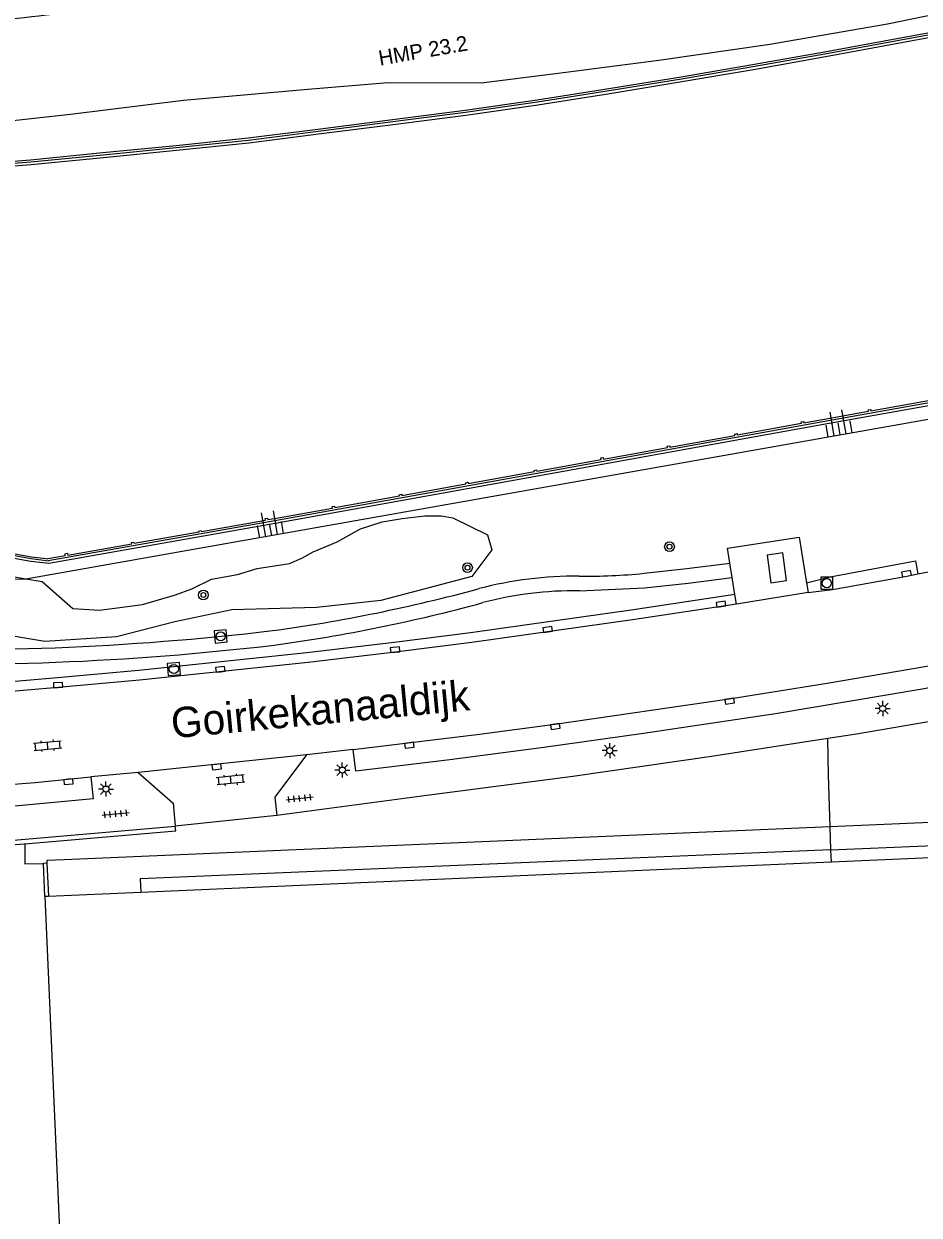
# Model space of a CAD drawing. Extents: x 132999 to 136000, y 398499 to 400501.
# Drawn here: x 133349.3 to 133423.1, y 398750.4 to 398848.7 of the extents above; entities that cross this region are included whole.
import ezdxf

# ---------------------------------------------------------------- set-up
doc = ezdxf.new("R2010")
doc.units = 0
for name, color, linetype in [('gg-afsc-hekwerk', 7, 'Continuous'), ('gg-afsc-muur', 7, 'Continuous'), ('gg-anno-openbare ruimte label', 7, 'Continuous'), ('gg-bbg-hoofdgebouw', 7, 'Continuous'), ('gg-bbg-luifel en loopbrug', 7, 'Continuous'), ('gg-bbg-onder overbouw', 7, 'Continuous'), ('gg-bbg-pand overbouw', 7, 'Continuous'), ('gg-knt-BGT kruinlijn', 7, 'Continuous'), ('gg-knt-verharding', 7, 'Continuous'), ('gg-knt-verharding nz', 7, 'Continuous'), ('gg-kwrk-betonelement', 7, 'Continuous'), ('gt-anno-nummer hm paal', 7, 'Continuous'), ('gt-grn-groengrens', 7, 'Continuous'), ('gt-symb-boom', 7, 'Continuous'), ('gt-symb-klinker verharding', 7, 'Continuous'), ('gt-symb-kolk', 7, 'Continuous'), ('gt-symb-lichtmast', 7, 'Continuous'), ('gt-symb-rioolschacht', 7, 'Continuous'), ('gt-symb-talud symbool', 7, 'Continuous'), ('gt-symb-tegel verharding', 7, 'Continuous'), ('gx-grn-maaiveld', 7, 'Continuous')]:
    doc.layers.add(name, color=color, linetype=linetype)

# ---------------------------------------------------------------- blocks, each defined once
blk = doc.blocks.new('gt0-TALUD_1')
at = {"layer": 'gt-symb-talud symbool'}
for p, q in [((-1, -1), (-1, 0)), ((-0.5, -2), (-0.5, 0)), ((0, -1), (0, 0)), ((0.5, -2), (0.5, 0)), ((1, -1), (1, 0))]:
    blk.add_line(p, q, dxfattribs=at)
blk = doc.blocks.new('gt0-RS')
at = {"layer": 'gt-symb-rioolschacht'}
blk.add_lwpolyline([(-0.5, -0.5), (0.5, -0.5), (0.5, 0.5), (-0.5, 0.5)], close=True, dxfattribs=at)
blk.add_circle((0, 0), 0.375, dxfattribs=at)
blk = doc.blocks.new('gt0-KOLK')
at = {"layer": 'gt-symb-kolk'}
blk.add_lwpolyline([(0, 0), (0.375, 0), (0.375, 0.4), (-0.375, 0.4), (-0.375, 0), (0, 0)], dxfattribs=at)
blk = doc.blocks.new('gt0-BOOM')
at = {"layer": 'gt-symb-boom'}
for radius in [0.4, 0.2]:
    blk.add_circle((0, 0), radius, dxfattribs=at)
blk = doc.blocks.new('gt0-LMAST')
at = {"layer": 'gt-symb-lichtmast'}
for p, q in [((-0.182, 0.173), (-0.447, 0.438)), ((-0.005, 0.246), (-0.005, 0.621)), ((0.172, 0.173), (0.437, 0.438)), ((-0.255, -0.004), (-0.63, -0.004)), ((-0.182, -0.181), (-0.447, -0.446)), ((-0.005, -0.254), (-0.005, -0.629)), ((0.437, -0.446), (0.172, -0.181)), ((0.245, -0.004), (0.62, -0.004))]:
    blk.add_line(p, q, dxfattribs=at)
blk.add_circle((-0.005, -0.004), 0.25, dxfattribs=at)
blk = doc.blocks.new('gt0-KL1')
at = {"layer": 'gt-symb-klinker verharding'}
for p, q in [((-1.15, 0.3), (1.15, 0.3)), ((-1, -0.3), (-1, 0.3)), ((-0.5, 0.3), (-0.5, 0.45)), ((0, -0.3), (0, 0.3)), ((0.5, 0.3), (0.5, 0.45)), ((1, -0.3), (1, 0.3)), ((-1.15, -0.3), (1.15, -0.3)), ((-0.5, -0.45), (-0.5, -0.3)), ((0.5, -0.45), (0.5, -0.3))]:
    blk.add_line(p, q, dxfattribs=at)
blk = doc.blocks.new('gt0-TEG1')
at = {"layer": 'gt-symb-tegel verharding'}
for p, q in [((-1.125, 0), (1.125, 0)), ((-0.9, -0.25), (-0.9, 0.25)), ((-0.45, -0.25), (-0.45, 0.25)), ((0, -0.25), (0, 0.25)), ((0.45, -0.25), (0.45, 0.25)), ((0.9, -0.25), (0.9, 0.25))]:
    blk.add_line(p, q, dxfattribs=at)

msp = doc.modelspace()

# ---------------------------------------------------------------- linework, layer by layer
at = {"layer": 'gg-afsc-hekwerk'}
for p, q in [((133361.818, 398782.084), (133361.767, 398782.456)), ((133415.867, 398780.523), (133415.805, 398782.401)), ((133349.346, 398780.995), (133361.818, 398782.084)), ((133415.901, 398779.498), (133415.867, 398780.523))]:
    msp.add_line(p, q, dxfattribs=at)
for points in [[(133415.609, 398789.703), (133415.609, 398789.722), (133417.98, 398790.069), (133423.912, 398791.103), (133446.77, 398795.458), (133462.485, 398798.488), (133468.883, 398799.753)], [(133415.805, 398782.401), (133415.664, 398786.661), (133415.609, 398789.703)], [(133293.847, 398778.301), (133296.188, 398778.325), (133308.274, 398778.577), (133322.783, 398779.123), (133337.252, 398780.056), (133349.303, 398780.991), (133349.346, 398780.995)], [(133349.346, 398780.995), (133349.358, 398779.359), (133350.893, 398779.37)]]:
    msp.add_lwpolyline(points, dxfattribs=at)
at = {"layer": 'gg-afsc-muur'}
msp.add_line((133351.01, 398776.646), (133350.893, 398779.37), dxfattribs=at)
for points in [[(133472.587, 398856.696), (133472.231, 398856.63), (133456.851, 398853.792), (133440.667, 398850.81), (133421.336, 398847.253), (133415.37, 398846.154), (133409.432, 398845.103), (133403.529, 398844.097), (133397.579, 398843.125), (133391.652, 398842.19), (133385.708, 398841.335), (133379.726, 398840.569), (133373.787, 398839.803), (133367.81, 398839.049), (133361.852, 398838.439), (133355.825, 398837.84), (133349.854, 398837.251), (133343.856, 398836.777), (133337.878, 398836.337)], [(133464.842, 398824.728), (133438.592, 398819.995), (133415.21, 398815.818), (133393.006, 398811.801), (133369.98, 398807.654), (133351.29, 398804.346)], [(133351.292, 398804.337), (133351.107, 398804.36), (133349.873, 398804.514), (133337.66, 398806.703)], [(133350.893, 398779.37), (133350.891, 398779.417), (133351.181, 398779.425)]]:
    msp.add_lwpolyline(points, dxfattribs=at)
at = {"layer": 'gg-bbg-hoofdgebouw'}
for p, q in [((133351.302, 398776.659), (133351.01, 398776.646)), ((133358.917, 398776.994), (133351.302, 398776.659))]:
    msp.add_line(p, q, dxfattribs=at)
msp.add_lwpolyline([(133351.01, 398776.646), (133353.201, 398726.602), (133355.607, 398671.444)], dxfattribs=at)
at = {"layer": 'gg-bbg-luifel en loopbrug'}
for p, q in [((133439.039, 398783.401), (133415.805, 398782.401)), ((133351.181, 398779.425), (133351.302, 398776.659))]:
    msp.add_line(p, q, dxfattribs=at)
msp.add_lwpolyline([(133415.805, 398782.401), (133352.611, 398779.682), (133351.174, 398779.618), (133351.181, 398779.425)], dxfattribs=at)
at = {"layer": 'gg-bbg-onder overbouw'}
for p, q in [((133439.39, 398780.53), (133415.901, 398779.498)), ((133415.901, 398779.498), (133358.917, 398776.994))]:
    msp.add_line(p, q, dxfattribs=at)
at = {"layer": 'gg-bbg-pand overbouw'}
for points in [[(133415.867, 398780.523), (133439.348, 398781.513), (133439.39, 398780.53)], [(133415.867, 398780.523), (133358.867, 398778.119), (133358.917, 398776.994)]]:
    msp.add_lwpolyline(points, dxfattribs=at)
at = {"layer": 'gg-knt-BGT kruinlijn'}
for p, q in [((133434.733, 398851.533), (133420.546, 398848.638)), ((133420.546, 398848.638), (133410.837, 398846.952)), ((133410.837, 398846.952), (133401.675, 398845.649)), ((133401.675, 398845.649), (133393.136, 398844.539)), ((133393.136, 398844.539), (133387.01, 398843.779)), ((133379.334, 398843.798), (133372.703, 398843.259)), ((133387.01, 398843.779), (133379.334, 398843.798)), ((133362.434, 398842.34), (133353.116, 398841.195)), ((133372.703, 398843.259), (133362.434, 398842.34)), ((133353.116, 398841.195), (133343.898, 398840.185))]:
    msp.add_line(p, q, dxfattribs=at)
for points in [[(133349.433, 398802.862), (133445.51, 398819.867), (133468.28, 398824.1)], [(133339.496, 398804.853), (133346.928, 398803.306), (133349.433, 398802.862)]]:
    msp.add_lwpolyline(points, dxfattribs=at)
at = {"layer": 'gg-knt-verharding'}
for p, q in [((133413.448, 398805.107), (133413.858, 398802.529)), ((133407.71, 398802.984), (133407.521, 398804.17)), ((133407.935, 398801.569), (133407.71, 398802.984)), ((133413.858, 398802.529), (133413.984, 398801.739)), ((133408.061, 398800.779), (133407.935, 398801.569)), ((133413.984, 398801.739), (133408.061, 398800.779)), ((133376.446, 398788.78), (133372.609, 398788.35)), ((133358.702, 398786.891), (133354.809, 398786.521)), ((133382.532, 398784.983), (133370.145, 398783.342)), ((133370.145, 398783.342), (133361.767, 398782.456))]:
    msp.add_line(p, q, dxfattribs=at)
for points in [[(133423.047, 398803.275), (133452.544, 398808.978), (133474.794, 398813.324)], [(133407.521, 398804.17), (133407.326, 398805.392), (133413.258, 398806.303), (133413.448, 398805.107)], [(133413.984, 398801.739), (133415.983, 398802.003), (133422.134, 398803.099), (133423.047, 398803.275)], [(133463.844, 398801.547), (133423.552, 398793.788), (133411.281, 398791.735), (133400.408, 398790.097), (133392.18, 398788.941), (133384.422, 398787.939), (133376.657, 398786.994), (133376.446, 398788.78)], [(133408.061, 398800.779), (133399.68, 398799.511), (133386.228, 398797.628), (133379.925, 398796.818), (133372.72, 398795.979), (133358.816, 398794.519), (133352.117, 398793.894), (133344.405, 398793.24), (133336.688, 398792.652), (133329.453, 398792.172), (133322.214, 398791.768), (133314.995, 398791.448), (133301.531, 398791.018)], [(133415.609, 398789.703), (133405.998, 398788.211), (133394.566, 398786.562), (133382.532, 398784.983)], [(133372.609, 398788.35), (133369.978, 398784.861), (133370.145, 398783.342)], [(133354.809, 398786.521), (133354.993, 398784.706), (133348.837, 398784.149), (133342.676, 398783.648), (133335.69, 398783.146), (133328.699, 398782.703), (133322.207, 398782.349), (133315.712, 398782.056), (133309.014, 398781.816), (133302.314, 398781.644), (133297.377, 398781.567)], [(133358.702, 398786.891), (133361.607, 398784.352), (133361.767, 398782.456)], [(133293.625, 398778.674), (133296.61, 398778.705), (133303.069, 398778.829), (133315.055, 398779.202), (133327.021, 398779.769), (133338.335, 398780.485), (133344.269, 398780.936), (133361.767, 398782.456)]]:
    msp.add_lwpolyline(points, dxfattribs=at)
msp.add_arc((133297.102, 399310.987), 464.733, 274.69579, 277.04022, dxfattribs=at)
at = {"layer": 'gg-knt-verharding nz'}
msp.add_line((133372.609, 398788.35), (133358.702, 398786.891), dxfattribs=at)
for points in [[(133376.446, 398788.78), (133386.883, 398790.046), (133393.094, 398790.882), (133407.471, 398792.974), (133415.547, 398794.27), (133423.613, 398795.63), (133464.293, 398803.482)], [(133297.321, 398783.36), (133301.036, 398783.42), (133308.5, 398783.612), (133315.537, 398783.857), (133322.572, 398784.175), (133330.011, 398784.598), (133337.447, 398785.086), (133350.204, 398786.068), (133354.809, 398786.521)]]:
    msp.add_lwpolyline(points, dxfattribs=at)
at = {"layer": 'gg-kwrk-betonelement'}
msp.add_lwpolyline([(133412.201, 398802.738), (133411.887, 398805.015), (133410.596, 398804.829), (133410.91, 398802.552), (133412.201, 398802.738)], dxfattribs=at)
at = {"layer": 'gt-grn-groengrens'}
msp.add_line((133369.941, 398797.406), (133369.92, 398797.403), dxfattribs=at)
for points in [[(133349.433, 398802.862), (133350.791, 398802.637), (133353.315, 398800.434), (133355.517, 398800.273), (133359.062, 398800.757), (133361.801, 398801.562), (133363.144, 398802.046), (133364.755, 398802.851), (133366.903, 398803.227), (133368.514, 398803.711), (133371.2, 398804.14), (133372.22, 398804.57), (133373.133, 398805.107), (133375.121, 398805.913), (133377.054, 398806.987), (133378.826, 398807.578), (133380.491, 398807.846), (133382.371, 398808.061), (133383.714, 398808.061), (133384.681, 398807.9), (133387.527, 398806.503), (133387.897, 398805.259), (133386.236, 398803.075), (133378.734, 398801.08), (133373.416, 398800.511), (133366.437, 398800.321), (133361.736, 398799.324), (133356.913, 398798.071), (133351.006, 398797.695), (133346.87, 398798.394)], [(133400.444, 398803.325), (133403.988, 398803.711), (133407.521, 398804.17)], [(133413.858, 398802.529), (133415.814, 398803.038), (133422.84, 398804.347), (133423.047, 398803.275)], [(133395.112, 398801.886), (133400.471, 398802.122), (133404.093, 398802.515), (133407.71, 398802.984)], [(133347.825, 398802.837), (133349.433, 398802.862)], [(133407.935, 398801.569), (133399.565, 398800.303), (133386.122, 398798.421), (133379.828, 398797.612), (133372.632, 398796.774), (133358.737, 398795.315), (133352.046, 398794.691), (133344.341, 398794.037), (133336.631, 398793.45), (133329.404, 398792.971), (133322.174, 398792.567), (133314.965, 398792.247), (133301.512, 398791.818)]]:
    msp.add_lwpolyline(points, dxfattribs=at)
for centre, radius, start, end in [((133394.817, 398771.442), 31.645, 89.48935, 104.61737), ((133395.54, 398853.106), 50.022, 269.49463, 275.62589), ((133351.77, 398930.798), 133.424, 277.75701, 285.2348), ((133394.829, 398771.359), 30.529, 89.46846, 104.58154), ((133351.782, 398930.751), 134.576, 277.75481, 285.23377), ((133343.169, 399023.022), 225.999, 267.64387, 276.76194), ((133343.168, 399023.096), 227.273, 267.64495, 276.75988)]:
    msp.add_arc(centre, radius, start, end, dxfattribs=at)
at = {"layer": 'gx-grn-maaiveld'}
for points in [[(133337.863, 398836.536), (133343.841, 398836.976), (133349.836, 398837.45), (133355.805, 398838.039), (133361.832, 398838.638), (133367.787, 398839.248), (133373.762, 398840.001), (133379.701, 398840.767), (133385.681, 398841.533), (133391.622, 398842.388), (133397.547, 398843.322), (133403.496, 398844.294), (133409.398, 398845.3), (133415.334, 398846.351), (133421.3, 398847.45), (133440.631, 398851.007), (133456.815, 398853.989), (133472.195, 398856.827), (133472.604, 398856.903)], [(133337.892, 398836.137), (133343.871, 398836.577), (133349.871, 398837.052), (133355.844, 398837.641), (133361.872, 398838.24), (133367.832, 398838.851), (133373.813, 398839.604), (133379.752, 398840.37), (133385.735, 398841.137), (133391.682, 398841.993), (133397.61, 398842.927), (133403.562, 398843.9), (133409.467, 398844.906), (133415.405, 398845.957), (133421.373, 398847.057), (133440.703, 398850.614), (133456.888, 398853.596), (133472.268, 398856.434), (133472.669, 398856.508)], [(133337.611, 398806.534), (133349.847, 398804.341), (133351.086, 398804.187), (133351.324, 398804.157), (133351.325, 398804.149), (133370.015, 398807.457), (133393.041, 398811.604), (133415.245, 398815.621), (133438.627, 398819.798), (133464.878, 398824.531)], [(133337.71, 398806.872), (133349.899, 398804.687), (133351.129, 398804.534), (133351.26, 398804.518), (133351.255, 398804.543), (133352.695, 398804.798), (133352.671, 398804.94), (133352.868, 398804.974), (133352.892, 398804.833), (133358.172, 398805.767), (133358.155, 398805.866), (133358.352, 398805.9), (133358.369, 398805.802), (133363.727, 398806.75), (133363.717, 398806.811), (133363.914, 398806.845), (133363.924, 398806.785), (133369.205, 398807.72), (133369.182, 398807.852), (133369.379, 398807.886), (133369.402, 398807.755), (133369.945, 398807.851), (133374.735, 398808.714), (133374.715, 398808.83), (133374.912, 398808.864), (133374.932, 398808.749), (133380.268, 398809.71), (133380.251, 398809.812), (133380.448, 398809.846), (133380.465, 398809.746), (133385.75, 398810.697), (133385.733, 398810.799), (133385.93, 398810.833), (133385.947, 398810.733), (133391.401, 398811.715), (133391.383, 398811.818), (133391.58, 398811.852), (133391.597, 398811.75), (133396.898, 398812.708), (133396.873, 398812.852), (133397.07, 398812.886), (133397.094, 398812.744), (133402.386, 398813.701), (133402.365, 398813.823), (133402.562, 398813.857), (133402.583, 398813.737), (133407.945, 398814.707), (133407.926, 398814.818), (133408.123, 398814.852), (133408.142, 398814.742), (133413.443, 398815.702), (133413.421, 398815.829), (133413.618, 398815.863), (133413.64, 398815.737), (133415.174, 398816.015), (133418.968, 398816.693), (133418.947, 398816.817), (133419.144, 398816.851), (133419.165, 398816.728), (133424.51, 398817.683)]]:
    msp.add_lwpolyline(points, dxfattribs=at)

# ---------------------------------------------------------------- block references
at = {"layer": 'gt-symb-boom'}
for p in [(133402.546, 398805.521), (133385.882, 398803.795), (133364.091, 398801.538)]:
    msp.add_blockref('gt0-BOOM', p, dxfattribs=at)
at = {"layer": 'gt-symb-klinker verharding'}
for p, rotation in [((133351.24, 398789.11), 5.106241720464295), ((133366.331, 398786.282), -174.03296237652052)]:
    msp.add_blockref('gt0-KL1', p, dxfattribs=dict(at, rotation=rotation))
at = {"layer": 'gt-symb-kolk'}
for p, rotation in [((133422.134, 398803.099), 10.099136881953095), ((133406.829, 398800.583), 7.700655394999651), ((133392.524, 398798.493), 8.049061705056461), ((133379.924, 398796.818), 5.739098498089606), ((133365.508, 398795.2), 5.910070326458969), ((133352.105, 398793.906), 3.0940580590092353), ((133407.47, 398792.974), -171.19719554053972), ((133393.094, 398790.882), -172.12907950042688), ((133381.062, 398789.338), -173.1094516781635), ((133365.166, 398787.555), -173.91299166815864), ((133352.942, 398786.33), -174.5460811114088)]:
    msp.add_blockref('gt0-KOLK', p, dxfattribs=dict(at, rotation=rotation))
at = {"layer": 'gt-symb-lichtmast'}
for p in [(133420.141, 398792.175), (133397.62, 398788.696), (133375.555, 398787.095), (133356.053, 398785.526)]:
    msp.add_blockref('gt0-LMAST', p, dxfattribs=at)
at = {"layer": 'gt-symb-rioolschacht'}
msp.add_blockref('gt0-RS', (133415.525, 398802.514), dxfattribs=at)
for p, rotation in [((133365.506, 398798.116), 4.992081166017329), ((133361.651, 398795.433), 4.877880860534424)]:
    msp.add_blockref('gt0-RS', p, dxfattribs=dict(at, rotation=rotation))
at = {"layer": 'gt-symb-talud symbool'}
for p, xscale, yscale, rotation in [((133416.608, 398814.752), 1.0004249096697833, 1.0004249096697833, -169.92566726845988), ((133369.696, 398806.432), 1.0002504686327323, 1.0002504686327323, -169.98206552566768)]:
    msp.add_blockref('gt0-TALUD_1', p, dxfattribs=dict(at, xscale=xscale, yscale=yscale, rotation=rotation))
at = {"layer": 'gt-symb-tegel verharding'}
for p, rotation in [((133372.03, 398784.755), 6.257933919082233), ((133356.848, 398783.474), 5.391463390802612)]:
    msp.add_blockref('gt0-TEG1', p, dxfattribs=dict(at, rotation=rotation))

# ---------------------------------------------------------------- texts
at = {"layer": 'gg-anno-openbare ruimte label'}
msp.add_text('Goirkekanaaldijk', height=2.5, rotation=5.4, dxfattribs=at).set_placement((133361.54, 398789.707))
at = {"layer": 'gt-anno-nummer hm paal'}
msp.add_text('HMP 23.2', height=1.25, rotation=9.90508, dxfattribs=at).set_placement((133378.659, 398845.206))

doc.saveas('drawing.dxf')
